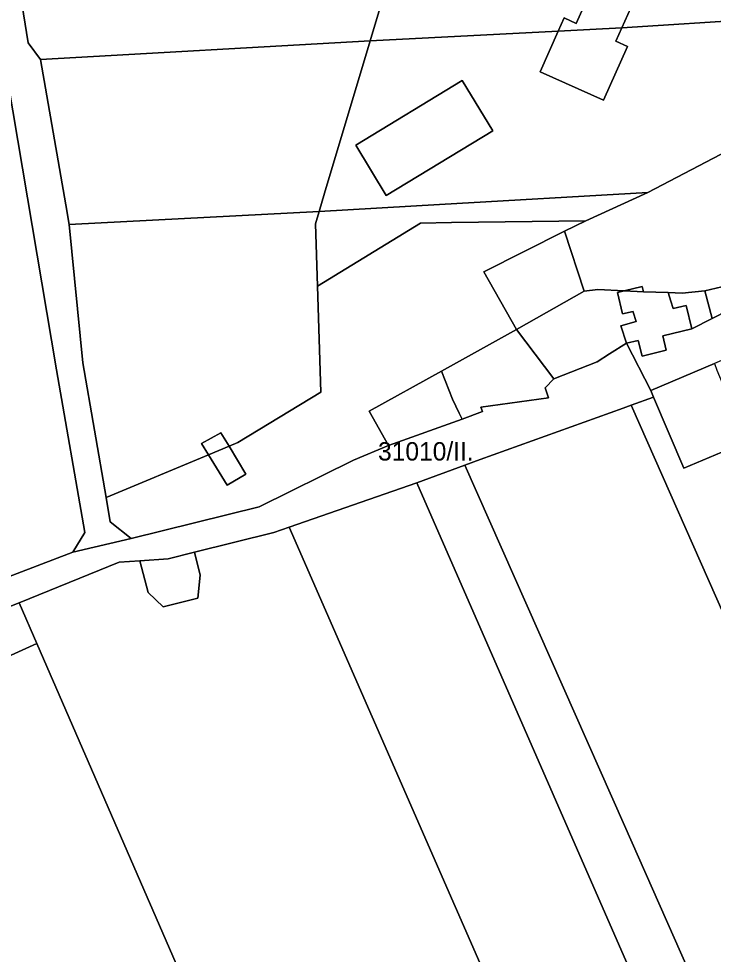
# Model space of a CAD drawing. Extents: x -541351 to -537540, y -1162694 to -1159725.
# Drawn here: x -540312.2 to -540123.3, y -1161301.7 to -1161047.3 of the extents above; entities that cross this region are included whole.
import ezdxf

# ---------------------------------------------------------------- set-up
doc = ezdxf.new("R2010")
doc.units = 0
for name, color, linetype in [('95560013', 7, 'Continuous'), ('95590013', 7, 'Continuous'), ('95610013', 7, 'Continuous'), ('95640013', 7, 'Continuous'), ('95660013', 7, 'Continuous')]:
    doc.layers.add(name, color=color, linetype=linetype)

msp = doc.modelspace()

# ---------------------------------------------------------------- linework, layer by layer
at = {"layer": '95560013'}
for points in [[(-540216.63, -1161053.39), (-540306.26, -1161058.41), (-540309.59, -1161053.9), (-540320.11, -1160989), (-540195.22, -1160981.77)], [(-540230.48, -1161099.76), (-540298.48, -1161103.29), (-540299.4, -1161097.97), (-540306.26, -1161058.41), (-540216.63, -1161053.39), (-540228.99, -1161094.76)], [(-540316.41, -1161056.82), (-540301.95, -1161142.81), (-540294.21, -1161187.08), (-540297.43, -1161192.42), (-540386.02, -1161226.29), (-540490.48, -1161267.79), (-540495.73, -1161264.57), (-540502.72, -1161202.63), (-540511.17, -1161133.39), (-540413.71, -1161095.07)], [(-540298.48, -1161103.29), (-540230.48, -1161099.76), (-540231.49, -1161103.13), (-540230.96, -1161120.03), (-540230.06, -1161148.91), (-540252.57, -1161162.6), (-540255, -1161163.61), (-540257.2, -1161159.96), (-540262.46, -1161162.85), (-540260.57, -1161165.94), (-540288.43, -1161177.55), (-540294.74, -1161140.88)], [(-540260.57, -1161165.94), (-540262.46, -1161162.85), (-540257.2, -1161159.96), (-540255, -1161163.61)], [(-540147.49, -1161266.69), (-540080.24, -1161418.65), (-540092.67, -1161427.78), (-540203.89, -1161173.54), (-540190.84, -1161168.71)], [(-540092.67, -1161427.78), (-540108.57, -1161439.09), (-540125.75, -1161443.43), (-540238.6, -1161185.61), (-540203.89, -1161173.54)], [(-540242.79, -1161187.03), (-540238.6, -1161185.61), (-540125.75, -1161443.43), (-540200.82, -1161461.87), (-540307.23, -1161217.26), (-540312.06, -1161206.17), (-540284.83, -1161195.14), (-540279.25, -1161194.73), (-540277.01, -1161203.38), (-540272.9, -1161207.24), (-540263.49, -1161204.92), (-540262.84, -1161198.63), (-540264.39, -1161192.38)], [(-540279.25, -1161194.73), (-540271.57, -1161194.17), (-540264.39, -1161192.38), (-540262.84, -1161198.63), (-540263.49, -1161204.92), (-540272.9, -1161207.24), (-540277.01, -1161203.38)], [(-540376.08, -1161248.51), (-540307.23, -1161217.26), (-540200.82, -1161461.87), (-540222.72, -1161467.24), (-540276.94, -1161480.65), (-540384.28, -1161234.82), (-540381.86, -1161234.02)]]:
    msp.add_lwpolyline(points, close=True, dxfattribs=at)
at = {"layer": '95590013'}
for points in [[(-540142.63, -1161120.16), (-540147.58, -1161121.37), (-540154.68, -1161120.99), (-540158.41, -1161121.41), (-540163.73, -1161105.11), (-540157.96, -1161102.34), (-540141.11, -1161094.63), (-540111.48, -1161079.08), (-540106.6, -1161096.26), (-540102.38, -1161104.26), (-540103.61, -1161116.53), (-540112.01, -1161119.83), (-540116.39, -1161119.21), (-540125.65, -1161121.32), (-540131.73, -1161121.98), (-540135.62, -1161121.84), (-540142.31, -1161121.58)], [(-540145.06, -1161127.15), (-540144.24, -1161129.7), (-540148.46, -1161130.89), (-540146.87, -1161135.53), (-540151.53, -1161138.45), (-540154.85, -1161140.64), (-540166.71, -1161145.31), (-540176.86, -1161131.88), (-540158.41, -1161121.41), (-540154.68, -1161120.99), (-540147.58, -1161121.37), (-540149.34, -1161121.79), (-540147.96, -1161127.6), (-540145.12, -1161126.95)], [(-540129.16, -1161131.68), (-540130.68, -1161125.32), (-540134.23, -1161126.19), (-540134.89, -1161124.15), (-540135.62, -1161121.84), (-540131.73, -1161121.98), (-540125.65, -1161121.32), (-540123.59, -1161128.82)], [(-540216.93, -1161154.09), (-540197.26, -1161143.19), (-540194.26, -1161150.84), (-540192.42, -1161154.61), (-540191.64, -1161156.26), (-540211.6, -1161163.37)], [(-540080.23, -1161245.02), (-540101.51, -1161252.18), (-540145.66, -1161152.44), (-540139.55, -1161150.22), (-540131.35, -1161169.58), (-540114.07, -1161162.27)], [(-540039.28, -1161388.94), (-540056, -1161401.07), (-540080.24, -1161418.65), (-540147.49, -1161266.69), (-540190.84, -1161168.71), (-540186.7, -1161167.22), (-540147.81, -1161153.21), (-540145.66, -1161152.44), (-540101.51, -1161252.18)], [(-540312.06, -1161206.17), (-540307.23, -1161217.26), (-540376.08, -1161248.51), (-540381.86, -1161234.02)]]:
    msp.add_lwpolyline(points, close=True, dxfattribs=at)
at = {"layer": '95610013'}
for points in [[(-540246.8, -1161180.03), (-540281.58, -1161188.7), (-540287.3, -1161184.12), (-540288.43, -1161177.55), (-540260.57, -1161165.94), (-540255.5, -1161174.21), (-540250.43, -1161171.17), (-540255, -1161163.61), (-540252.57, -1161162.6), (-540230.06, -1161148.91), (-540230.96, -1161120.03), (-540202.91, -1161102.9), (-540194.5, -1161102.8), (-540157.96, -1161102.34), (-540163.73, -1161105.11), (-540185.73, -1161116.2), (-540176.86, -1161131.88), (-540197.26, -1161143.19), (-540216.93, -1161154.09), (-540211.6, -1161163.37), (-540221.12, -1161167.34)], [(-540163.73, -1161105.11), (-540158.41, -1161121.41), (-540176.86, -1161131.88), (-540185.73, -1161116.2)], [(-540250.43, -1161171.17), (-540255.5, -1161174.21), (-540260.57, -1161165.94), (-540255, -1161163.61)]]:
    msp.add_lwpolyline(points, close=True, dxfattribs=at)
at = {"layer": '95640013'}
for points in [[(-540133.71, -1161017.85), (-540118.19, -1160983.23), (-540129.1, -1160978.34), (-540160.6, -1161048.61), (-540163.86, -1161047.15), (-540165.48, -1161050.77), (-540216.63, -1161053.39), (-540195.22, -1160981.77), (-540091.12, -1160975.75), (-540102.04, -1161001.75), (-540111.72, -1161043.54), (-540111.44, -1161047.5), (-540148.21, -1161049.83), (-540137.6, -1161026.16), (-540128.29, -1161030.33), (-540124.54, -1161021.96)], [(-540165.48, -1161050.77), (-540163.86, -1161047.15), (-540160.6, -1161048.61), (-540129.1, -1160978.34), (-540118.19, -1160983.23), (-540133.71, -1161017.85), (-540124.54, -1161021.96), (-540128.29, -1161030.33), (-540137.6, -1161026.16), (-540148.21, -1161049.83), (-540156.84, -1161050.3)], [(-540230.48, -1161099.76), (-540228.99, -1161094.76), (-540216.63, -1161053.39), (-540165.48, -1161050.77), (-540170.41, -1161061.76), (-540153.17, -1161069.49), (-540146.62, -1161054.88), (-540149.83, -1161053.44), (-540148.21, -1161049.83), (-540111.44, -1161047.5), (-540108.61, -1161069.28), (-540107.61, -1161077.15), (-540111.48, -1161079.08), (-540141.11, -1161094.63), (-540197.72, -1161097.88)], [(-540149.83, -1161053.44), (-540146.62, -1161054.88), (-540153.17, -1161069.49), (-540170.41, -1161061.76), (-540165.48, -1161050.77), (-540156.84, -1161050.3), (-540148.21, -1161049.83)], [(-540183.26, -1161077.85), (-540212.24, -1161095.43), (-540220.54, -1161081.75), (-540191.56, -1161064.17)], [(-540191.56, -1161064.17), (-540220.54, -1161081.75), (-540212.24, -1161095.43), (-540183.26, -1161077.85)], [(-540230.96, -1161120.03), (-540231.49, -1161103.13), (-540230.48, -1161099.76), (-540197.72, -1161097.88), (-540141.11, -1161094.63), (-540157.96, -1161102.34), (-540194.5, -1161102.8), (-540202.91, -1161102.9)], [(-540099.82, -1161116.69), (-540087.01, -1161125.82), (-540091.68, -1161127.8), (-540107.65, -1161134.58), (-540123.02, -1161141.1), (-540140.3, -1161148.43), (-540146.87, -1161135.53), (-540143.71, -1161134.83), (-540142.66, -1161139.07), (-540136.1, -1161137.44), (-540137.01, -1161133.62), (-540129.16, -1161131.68), (-540123.59, -1161128.82), (-540114.93, -1161124.38), (-540114.6, -1161125.62), (-540107.04, -1161120.37)], [(-540125.65, -1161121.32), (-540116.39, -1161119.21), (-540114.93, -1161124.38), (-540123.59, -1161128.82)], [(-540130.68, -1161125.32), (-540129.16, -1161131.68), (-540137.01, -1161133.62), (-540136.1, -1161137.44), (-540142.66, -1161139.07), (-540143.71, -1161134.83), (-540146.87, -1161135.53), (-540148.46, -1161130.89), (-540144.24, -1161129.7), (-540145.06, -1161127.15), (-540145.12, -1161126.95), (-540147.96, -1161127.6), (-540149.34, -1161121.79), (-540147.58, -1161121.37), (-540142.31, -1161121.58), (-540135.62, -1161121.84), (-540134.89, -1161124.15), (-540134.23, -1161126.19)], [(-540142.63, -1161120.16), (-540142.31, -1161121.58), (-540147.58, -1161121.37)], [(-540176.86, -1161131.88), (-540166.71, -1161145.31), (-540169.06, -1161147.69), (-540168.14, -1161150.44), (-540186.48, -1161153), (-540186.06, -1161154.17), (-540191.64, -1161156.26), (-540192.42, -1161154.61), (-540194.26, -1161150.84), (-540197.26, -1161143.19)], [(-540140.3, -1161148.43), (-540123.02, -1161141.1), (-540122.37, -1161142.91), (-540118.22, -1161152.62), (-540114.07, -1161162.27), (-540131.35, -1161169.58), (-540139.55, -1161150.22)]]:
    msp.add_lwpolyline(points, close=True, dxfattribs=at)
for points in [[(-540320.11, -1160989), (-540309.59, -1161053.9), (-540306.26, -1161058.41), (-540299.4, -1161097.97), (-540298.48, -1161103.29), (-540294.74, -1161140.88), (-540288.43, -1161177.55), (-540287.3, -1161184.12), (-540281.58, -1161188.7), (-540297.43, -1161192.42), (-540294.21, -1161187.08), (-540301.95, -1161142.81), (-540316.41, -1161056.82)], [(-540386.02, -1161226.29), (-540297.43, -1161192.42), (-540281.58, -1161188.7), (-540246.8, -1161180.03), (-540221.12, -1161167.34), (-540211.6, -1161163.37), (-540191.64, -1161156.26), (-540186.06, -1161154.17), (-540186.48, -1161153), (-540168.14, -1161150.44), (-540169.06, -1161147.69), (-540166.71, -1161145.31), (-540154.85, -1161140.64), (-540151.53, -1161138.45), (-540146.87, -1161135.53), (-540140.3, -1161148.43), (-540139.55, -1161150.22), (-540145.66, -1161152.44), (-540147.81, -1161153.21), (-540186.7, -1161167.22), (-540190.84, -1161168.71), (-540203.89, -1161173.54), (-540238.6, -1161185.61), (-540242.79, -1161187.03), (-540264.39, -1161192.38), (-540271.57, -1161194.17), (-540279.25, -1161194.73), (-540284.83, -1161195.14), (-540312.06, -1161206.17), (-540381.86, -1161234.02)]]:
    msp.add_lwpolyline(points, dxfattribs=at)

# ---------------------------------------------------------------- texts
at = {"layer": '95660013'}
msp.add_text('31010/II.', height=5, rotation=0, dxfattribs=at).set_placement((-540214.48, -1161167.48))

doc.saveas('drawing.dxf')
